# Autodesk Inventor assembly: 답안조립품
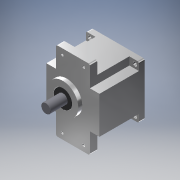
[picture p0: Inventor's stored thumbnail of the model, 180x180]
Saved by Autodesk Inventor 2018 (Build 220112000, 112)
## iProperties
Created: 2020-07
Part Number: 답안조립품
Material: 일반
Document SubType Name: Assembly
Designer: Admin
Author: Admin
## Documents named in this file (10)
- C:\Users\Admin\Desktop\700707V1014\답안조립품.iam
- C:\Users\Admin\Desktop\700707V1014\본체.ipt
- C:\Users\Admin\Desktop\700707V1014\커버.ipt
- C:\Users\Admin\Desktop\700707V1014\베어링 6003.ipt
- C:\Users\Admin\Desktop\700707V1014\베어링 608.ipt
- C:\Users\Admin\Desktop\700707V1014\메인 축.ipt
- C:\Users\Admin\Desktop\700707V1014\서브 축.ipt
- C:\Users\Admin\Desktop\700707V1014\볼트 M4.ipt
- C:\Users\Admin\Desktop\700707V1014\오일 실 17 32 8.ipt
- C:\Users\Admin\Desktop\700707V1014\오일 실 8 22 7.ipt
